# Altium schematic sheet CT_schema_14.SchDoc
size 145 x 119 mm
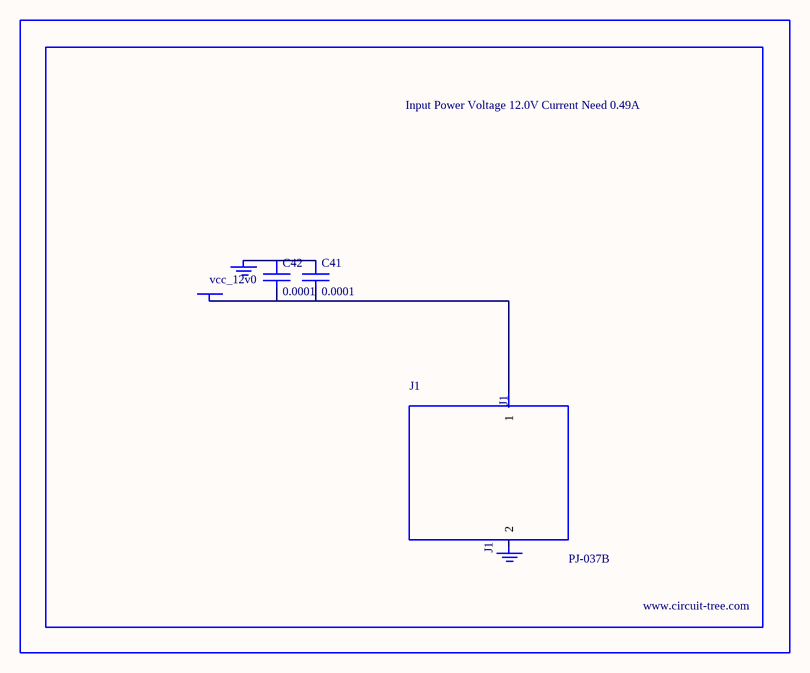
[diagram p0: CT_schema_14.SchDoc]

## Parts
BORDER13  (no value)
C41  0.0001  [EXV-9H]
C42  0.0001  [EXV-9H]
GND_INSTANCE_13_0  (no value)
GND_INSTANCE_13_1  (no value)
J1  PJ-037B  [PJ-037B_PACKAGE]
POWER_INSTANCE_13_0  vcc_12v0

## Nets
NetC41_1: C41.1 C42.1 GND_INSTANCE_13_0.0(GND)
NetC41_2: C41.2 C42.2 J1.1 POWER_INSTANCE_13_0.0(PWR)

Not connected (* = marked no-connect by the designer): GND_INSTANCE_13_1 0(GND); J1 2

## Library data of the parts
BORDER13 = BORDER_PAGE13
C41 C42 = EDK107M035A9HAA
GND_INSTANCE_13_0 GND_INSTANCE_13_1 = GND
POWER_INSTANCE_13_0 = PWR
